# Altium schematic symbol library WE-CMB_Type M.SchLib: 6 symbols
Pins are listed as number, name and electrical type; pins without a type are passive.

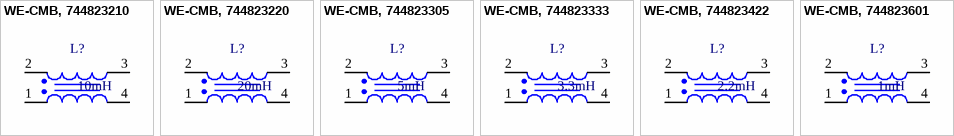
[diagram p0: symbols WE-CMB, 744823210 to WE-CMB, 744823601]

## WE-CMB, 744823210
designator L?, comment 10mH
WE-CMB Common Mode Power Line Choke, Type M, 10mH; PartNumber: 744823210
footprint WE-CMB_Type M_744823210
pins: 1, 2, 3, 4

## WE-CMB, 744823220
designator L?, comment 20mH
WE-CMB Common Mode Power Line Choke, Type M, 20mH; PartNumber: 744823220
footprint WE-CMB_Type M_744823220
pins: 1, 2, 3, 4

## WE-CMB, 744823305
designator L?, comment 5mH
WE-CMB Common Mode Power Line Choke, Type M, 5mH; PartNumber: 744823305
footprint WE-CMB_Type M_744823305
pins: 1, 2, 3, 4

## WE-CMB, 744823333
designator L?, comment 3.3mH
WE-CMB Common Mode Power Line Choke, Type M, 3.3mH; PartNumber: 744823333
footprint WE-CMB_Type M_744823333
pins: 1, 2, 3, 4

## WE-CMB, 744823422
designator L?, comment 2.2mH
WE-CMB Common Mode Power Line Choke, Type M, 2.2mH; PartNumber: 744823422
footprint WE-CMB_Type M_744823422
pins: 1, 2, 3, 4

## WE-CMB, 744823601
designator L?, comment 1mH
WE-CMB Common Mode Power Line Choke, Type M, 1mH; PartNumber: 744823601
footprint WE-CMB_Type M_744823601
pins: 1, 2, 3, 4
